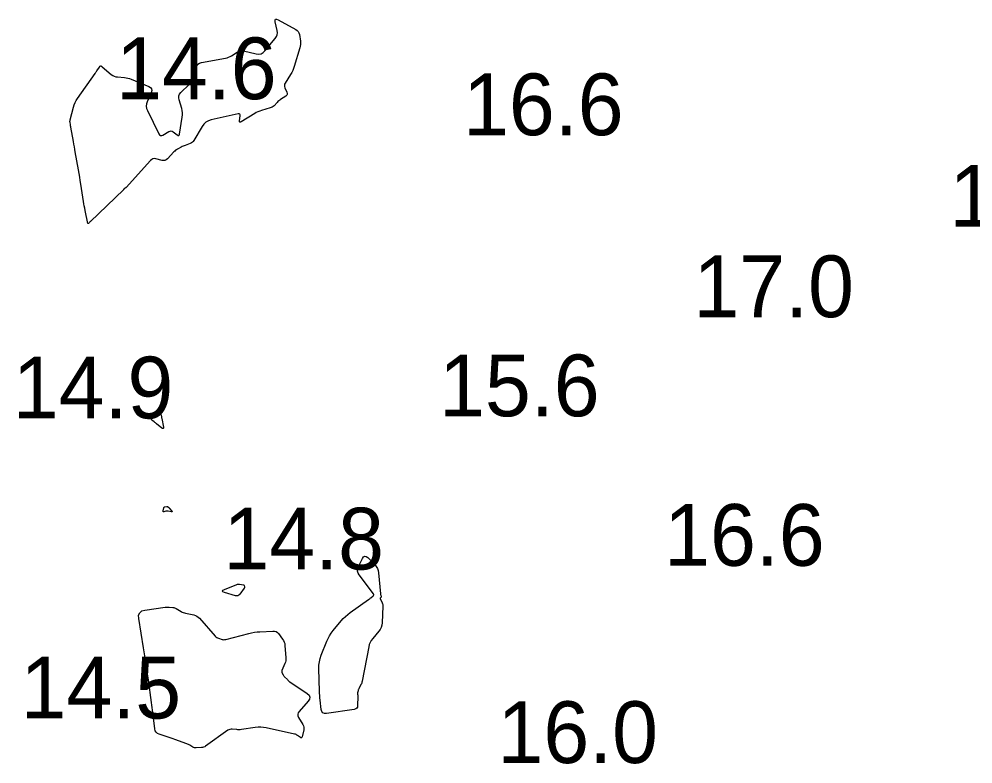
# Model space of a CAD drawing. Extents: x 3040093 to 3056816, y 408076 to 509144.
# Drawn here: x 3044731.9 to 3044809.2, y 434643.6 to 434703.9 of the extents above; entities that cross this region are included whole.
import ezdxf

# ---------------------------------------------------------------- set-up
doc = ezdxf.new("R2010")
doc.units = 0
doc.layers.add('V-CHAN-CONT-EL15', color=7, linetype='Continuous')
doc.layers.add('V-TOPO-SOUN-0810', color=7, linetype='Continuous')

msp = doc.modelspace()

# ---------------------------------------------------------------- linework, layer by layer
at = {"layer": 'V-CHAN-CONT-EL15'}
for points in [[(3044754.701, 434701.97), (3044754.699, 434701.836), (3044754.682, 434701.702), (3044754.65, 434701.57), (3044754.191, 434700.05), (3044754.135, 434699.885), (3044754.069, 434699.725), (3044753.992, 434699.569), (3044753.904, 434699.419), (3044753.457, 434698.705), (3044753.414, 434698.617), (3044753.396, 434698.527), (3044753.402, 434698.435), (3044753.433, 434698.342), (3044753.606, 434697.966), (3044753.634, 434697.876), (3044753.628, 434697.796), (3044753.59, 434697.725), (3044753.52, 434697.664), (3044753.093, 434697.382), (3044753.017, 434697.329), (3044752.945, 434697.272), (3044752.876, 434697.212), (3044752.811, 434697.147), (3044752.556, 434696.881), (3044752.489, 434696.819), (3044752.416, 434696.768), (3044752.336, 434696.727), (3044752.251, 434696.697), (3044751.542, 434696.495), (3044751.397, 434696.448), (3044751.256, 434696.391), (3044751.119, 434696.325), (3044750.987, 434696.248), (3044749.903, 434695.57), (3044749.829, 434695.535), (3044749.78, 434695.539), (3044749.757, 434695.582), (3044749.759, 434695.664), (3044749.817, 434696.068), (3044749.818, 434696.154), (3044749.79, 434696.208), (3044749.733, 434696.232), (3044749.647, 434696.226), (3044747.464, 434695.74), (3044747.233, 434695.665), (3044747.032, 434695.549), (3044746.861, 434695.393), (3044746.72, 434695.195), (3044746.066, 434694.068), (3044746.009, 434693.985), (3044745.94, 434693.916), (3044745.86, 434693.861), (3044745.769, 434693.819), (3044745.351, 434693.668), (3044745.269, 434693.637), (3044745.188, 434693.602), (3044745.109, 434693.565), (3044745.031, 434693.526), (3044744.721, 434693.361), (3044744.645, 434693.316), (3044744.575, 434693.266), (3044744.508, 434693.211), (3044744.446, 434693.149), (3044743.914, 434692.575), (3044743.821, 434692.496), (3044743.718, 434692.448), (3044743.605, 434692.432), (3044743.483, 434692.449), (3044742.977, 434692.58), (3044742.855, 434692.596), (3044742.743, 434692.58), (3044742.641, 434692.532), (3044742.548, 434692.451), (3044740.564, 434690.262), (3044740.548, 434690.245), (3044740.531, 434690.228), (3044740.513, 434690.212), (3044740.495, 434690.197), (3044740.42, 434690.139), (3044740.402, 434690.124), (3044740.383, 434690.108), (3044740.366, 434690.093), (3044740.348, 434690.076), (3044737.67, 434687.507), (3044737.661, 434687.498), (3044737.652, 434687.489), (3044737.644, 434687.479), (3044737.636, 434687.47), (3044737.605, 434687.43), (3044737.597, 434687.421), (3044737.589, 434687.412), (3044737.581, 434687.403), (3044737.571, 434687.394), (3044737.51, 434687.339), (3044737.498, 434687.331), (3044737.488, 434687.33), (3044737.481, 434687.336), (3044737.476, 434687.35), (3044737.251, 434688.4), (3044737.214, 434688.581), (3044737.179, 434688.762), (3044737.147, 434688.944), (3044737.117, 434689.127), (3044736.9, 434690.518), (3044736.853, 434690.81), (3044736.805, 434691.103), (3044736.756, 434691.395), (3044736.705, 434691.687), (3044736.448, 434693.136), (3044736.411, 434693.345), (3044736.373, 434693.555), (3044736.336, 434693.765), (3044736.298, 434693.975), (3044736.088, 434695.133), (3044736.079, 434695.183), (3044736.071, 434695.233), (3044736.062, 434695.284), (3044736.054, 434695.334), (3044736.022, 434695.535), (3044736.017, 434695.586), (3044736.016, 434695.636), (3044736.021, 434695.685), (3044736.032, 434695.735), (3044736.3, 434696.77), (3044736.357, 434696.955), (3044736.43, 434697.133), (3044736.518, 434697.304), (3044736.623, 434697.467), (3044738.049, 434699.495), (3044738.085, 434699.547), (3044738.122, 434699.598), (3044738.158, 434699.65), (3044738.195, 434699.701), (3044738.407, 434699.996), (3044738.411, 434700.002), (3044738.415, 434700.01), (3044738.418, 434700.018), (3044738.419, 434700.026), (3044738.425, 434700.059), (3044738.427, 434700.066), (3044738.431, 434700.072), (3044738.436, 434700.076), (3044738.444, 434700.079), (3044738.529, 434700.1), (3044738.539, 434700.101), (3044738.548, 434700.1), (3044738.555, 434700.096), (3044738.563, 434700.089), (3044738.589, 434700.059), (3044738.596, 434700.051), (3044738.604, 434700.044), (3044738.611, 434700.037), (3044738.619, 434700.031), (3044739.368, 434699.415), (3044739.481, 434699.335), (3044739.602, 434699.275), (3044739.731, 434699.233), (3044739.867, 434699.211), (3044740.43, 434699.16), (3044740.57, 434699.143), (3044740.707, 434699.115), (3044740.841, 434699.077), (3044740.973, 434699.029), (3044742.402, 434698.447), (3044742.553, 434698.358), (3044742.638, 434698.243), (3044742.656, 434698.101), (3044742.607, 434697.932), (3044742.277, 434697.204), (3044742.216, 434697.023), (3044742.198, 434696.842), (3044742.222, 434696.662), (3044742.289, 434696.482), (3044743.222, 434694.604), (3044743.285, 434694.511), (3044743.362, 434694.464), (3044743.453, 434694.462), (3044743.556, 434694.505), (3044744.041, 434694.793), (3044744.128, 434694.831), (3044744.214, 434694.84), (3044744.298, 434694.819), (3044744.379, 434694.77), (3044744.702, 434694.513), (3044744.775, 434694.469), (3044744.832, 434694.467), (3044744.872, 434694.507), (3044744.897, 434694.588), (3044745.123, 434695.951), (3044745.142, 434696.13), (3044745.14, 434696.307), (3044745.118, 434696.483), (3044745.074, 434696.657), (3044744.859, 434697.351), (3044744.828, 434697.519), (3044744.843, 434697.674), (3044744.905, 434697.818), (3044745.013, 434697.95), (3044745.691, 434698.603), (3044745.815, 434698.739), (3044745.916, 434698.888), (3044745.994, 434699.049), (3044746.051, 434699.224), (3044746.232, 434699.947), (3044746.295, 434700.109), (3044746.392, 434700.235), (3044746.524, 434700.324), (3044746.69, 434700.375), (3044748.616, 434700.727), (3044748.748, 434700.758), (3044748.876, 434700.801), (3044748.998, 434700.858), (3044749.115, 434700.927), (3044749.573, 434701.23), (3044749.69, 434701.292), (3044749.811, 434701.328), (3044749.938, 434701.337), (3044750.069, 434701.319), (3044751.104, 434701.08), (3044751.312, 434701.058), (3044751.501, 434701.091), (3044751.671, 434701.179), (3044751.823, 434701.323), (3044752.66, 434702.331), (3044752.756, 434702.474), (3044752.813, 434702.627), (3044752.832, 434702.789), (3044752.812, 434702.961), (3044752.657, 434703.665), (3044752.642, 434703.809), (3044752.677, 434703.886), (3044752.762, 434703.898), (3044752.895, 434703.844), (3044754.326, 434703.056), (3044754.435, 434702.981), (3044754.518, 434702.888), (3044754.575, 434702.778), (3044754.608, 434702.651), (3044754.689, 434702.106)], [(3044743.433, 434671.644), (3044743.44, 434671.606), (3044743.455, 434671.531), (3044743.586, 434670.848), (3044743.594, 434670.761), (3044743.575, 434670.719), (3044743.528, 434670.722), (3044743.455, 434670.769), (3044743.025, 434671.117), (3044742.981, 434671.153), (3044742.936, 434671.189), (3044742.891, 434671.225), (3044742.846, 434671.262), (3044742.655, 434671.415), (3044742.626, 434671.447), (3044742.615, 434671.48), (3044742.622, 434671.514), (3044742.648, 434671.549), (3044742.829, 434671.732), (3044742.844, 434671.746), (3044742.861, 434671.757), (3044742.879, 434671.766), (3044742.898, 434671.773), (3044742.979, 434671.794), (3044742.999, 434671.799), (3044743.019, 434671.805), (3044743.039, 434671.81), (3044743.059, 434671.816), (3044743.309, 434671.886), (3044743.342, 434671.891), (3044743.368, 434671.883), (3044743.386, 434671.863), (3044743.397, 434671.832)], [(3044744.044, 434664.306), (3044744.06, 434664.289), (3044744.076, 434664.271), (3044744.091, 434664.253), (3044744.265, 434664.04), (3044744.288, 434664.004), (3044744.29, 434663.982), (3044744.269, 434663.972), (3044744.227, 434663.975), (3044743.967, 434664.023), (3044743.924, 434664.029), (3044743.882, 434664.03), (3044743.84, 434664.027), (3044743.798, 434664.021), (3044743.63, 434663.985), (3044743.594, 434663.983), (3044743.572, 434663.993), (3044743.562, 434664.016), (3044743.566, 434664.051), (3044743.625, 434664.301), (3044743.637, 434664.332), (3044743.655, 434664.356), (3044743.68, 434664.373), (3044743.712, 434664.383), (3044743.877, 434664.411), (3044743.9, 434664.413), (3044743.921, 434664.409), (3044743.94, 434664.4), (3044743.958, 434664.387), (3044744.027, 434664.322)], [(3044761.246, 434657.099), (3044761.245, 434657.084), (3044761.239, 434657.069), (3044761.227, 434657.056), (3044761.173, 434657.005), (3044761.162, 434656.992), (3044761.156, 434656.977), (3044761.156, 434656.962), (3044761.161, 434656.946), (3044761.323, 434656.601), (3044761.349, 434656.537), (3044761.366, 434656.472), (3044761.376, 434656.405), (3044761.377, 434656.336), (3044761.326, 434654.977), (3044761.304, 434654.791), (3044761.252, 434654.616), (3044761.17, 434654.453), (3044761.058, 434654.302), (3044760.552, 434653.721), (3044760.437, 434653.57), (3044760.345, 434653.408), (3044760.275, 434653.235), (3044760.228, 434653.051), (3044759.702, 434650.27), (3044759.685, 434650.194), (3044759.662, 434650.121), (3044759.634, 434650.049), (3044759.6, 434649.979), (3044759.419, 434649.634), (3044759.402, 434649.599), (3044759.388, 434649.564), (3044759.376, 434649.528), (3044759.367, 434649.491), (3044759.328, 434649.312), (3044759.324, 434649.289), (3044759.322, 434649.266), (3044759.324, 434649.243), (3044759.327, 434649.22), (3044759.347, 434649.127), (3044759.351, 434649.104), (3044759.353, 434649.08), (3044759.355, 434649.057), (3044759.355, 434649.033), (3044759.333, 434648.282), (3044759.313, 434648.163), (3044759.261, 434648.073), (3044759.177, 434648.011), (3044759.061, 434647.977), (3044756.809, 434647.646), (3044756.643, 434647.646), (3044756.517, 434647.699), (3044756.433, 434647.806), (3044756.389, 434647.966), (3044756.296, 434648.714), (3044756.275, 434648.901), (3044756.258, 434649.089), (3044756.246, 434649.277), (3044756.239, 434649.465), (3044756.192, 434651.262), (3044756.198, 434651.546), (3044756.233, 434651.825), (3044756.296, 434652.099), (3044756.388, 434652.369), (3044756.834, 434653.496), (3044756.936, 434653.727), (3044757.055, 434653.948), (3044757.191, 434654.158), (3044757.345, 434654.359), (3044757.994, 434655.14), (3044758.162, 434655.329), (3044758.341, 434655.506), (3044758.532, 434655.671), (3044758.733, 434655.823), (3044760.212, 434656.869), (3044760.261, 434656.904), (3044760.309, 434656.94), (3044760.356, 434656.976), (3044760.403, 434657.014), (3044760.59, 434657.166), (3044760.626, 434657.205), (3044760.642, 434657.247), (3044760.637, 434657.291), (3044760.611, 434657.338), (3044759.452, 434658.865), (3044759.362, 434659.019), (3044759.321, 434659.178), (3044759.329, 434659.342), (3044759.387, 434659.511), (3044759.719, 434660.198), (3044759.808, 434660.331), (3044759.91, 434660.388), (3044760.025, 434660.368), (3044760.154, 434660.272), (3044760.719, 434659.707), (3044760.843, 434659.561), (3044760.936, 434659.401), (3044760.999, 434659.226), (3044761.032, 434659.038), (3044761.183, 434657.331), (3044761.186, 434657.305), (3044761.19, 434657.279), (3044761.197, 434657.254), (3044761.204, 434657.229), (3044761.243, 434657.116)], [(3044750.097, 434658.056), (3044750.116, 434658.043), (3044750.129, 434658.024), (3044750.137, 434658.001), (3044750.159, 434657.894), (3044750.162, 434657.868), (3044750.16, 434657.843), (3044750.152, 434657.82), (3044750.138, 434657.797), (3044749.773, 434657.301), (3044749.702, 434657.226), (3044749.621, 434657.182), (3044749.529, 434657.168), (3044749.427, 434657.184), (3044748.553, 434657.444), (3044748.416, 434657.5), (3044748.368, 434657.561), (3044748.41, 434657.625), (3044748.541, 434657.694), (3044749.533, 434658.097), (3044749.59, 434658.116), (3044749.648, 434658.126), (3044749.707, 434658.128), (3044749.766, 434658.121), (3044750.073, 434658.064)], [(3044753.687, 434650.335), (3044753.739, 434650.29), (3044753.793, 434650.247), (3044753.85, 434650.206), (3044755.241, 434649.254), (3044755.391, 434649.117), (3044755.453, 434648.968), (3044755.429, 434648.809), (3044755.317, 434648.64), (3044754.589, 434647.816), (3044754.51, 434647.7), (3044754.477, 434647.58), (3044754.488, 434647.456), (3044754.543, 434647.328), (3044754.888, 434646.752), (3044754.938, 434646.647), (3044754.967, 434646.538), (3044754.974, 434646.427), (3044754.959, 434646.311), (3044754.831, 434645.744), (3044754.811, 434645.69), (3044754.781, 434645.663), (3044754.741, 434645.664), (3044754.691, 434645.693), (3044754.47, 434645.862), (3044754.413, 434645.901), (3044754.353, 434645.933), (3044754.29, 434645.959), (3044754.223, 434645.977), (3044751.909, 434646.481), (3044751.692, 434646.518), (3044751.475, 434646.536), (3044751.257, 434646.533), (3044751.038, 434646.511), (3044749.91, 434646.344), (3044749.817, 434646.333), (3044749.724, 434646.328), (3044749.631, 434646.329), (3044749.538, 434646.335), (3044749.165, 434646.373), (3044749.073, 434646.375), (3044748.987, 434646.36), (3044748.904, 434646.33), (3044748.825, 434646.284), (3044747.015, 434644.999), (3044746.935, 434644.95), (3044746.851, 434644.914), (3044746.762, 434644.89), (3044746.669, 434644.879), (3044746.24, 434644.856), (3044746.17, 434644.858), (3044746.103, 434644.869), (3044746.039, 434644.891), (3044745.977, 434644.922), (3044745.736, 434645.07), (3044745.674, 434645.105), (3044745.611, 434645.137), (3044745.547, 434645.166), (3044745.481, 434645.191), (3044744.527, 434645.53), (3044744.368, 434645.586), (3044744.209, 434645.641), (3044744.05, 434645.695), (3044743.89, 434645.748), (3044743.251, 434645.957), (3044743.108, 434646.024), (3044743.001, 434646.119), (3044742.928, 434646.243), (3044742.89, 434646.396), (3044742.729, 434647.712), (3044742.704, 434647.917), (3044742.678, 434648.122), (3044742.652, 434648.327), (3044742.625, 434648.532), (3044742.518, 434649.351), (3044742.49, 434649.556), (3044742.462, 434649.761), (3044742.432, 434649.965), (3044742.402, 434650.17), (3044742.171, 434651.679), (3044742.122, 434651.998), (3044742.073, 434652.318), (3044742.023, 434652.637), (3044741.972, 434652.957), (3044741.59, 434655.339), (3044741.585, 434655.606), (3044741.668, 434655.809), (3044741.838, 434655.948), (3044742.094, 434656.023), (3044743.746, 434656.257), (3044743.821, 434656.265), (3044743.896, 434656.27), (3044743.972, 434656.27), (3044744.047, 434656.266), (3044744.348, 434656.243), (3044744.422, 434656.233), (3044744.494, 434656.215), (3044744.562, 434656.188), (3044744.628, 434656.153), (3044745.017, 434655.914), (3044745.105, 434655.865), (3044745.196, 434655.824), (3044745.291, 434655.792), (3044745.388, 434655.767), (3044746.043, 434655.631), (3044746.18, 434655.592), (3044746.304, 434655.532), (3044746.417, 434655.453), (3044746.519, 434655.354), (3044747.793, 434653.895), (3044747.848, 434653.841), (3044747.908, 434653.796), (3044747.974, 434653.76), (3044748.045, 434653.734), (3044748.345, 434653.647), (3044748.42, 434653.63), (3044748.495, 434653.624), (3044748.57, 434653.628), (3044748.645, 434653.642), (3044750.523, 434654.13), (3044750.741, 434654.18), (3044750.96, 434654.22), (3044751.181, 434654.248), (3044751.404, 434654.265), (3044752.467, 434654.319), (3044752.6, 434654.311), (3044752.718, 434654.274), (3044752.824, 434654.207), (3044752.915, 434654.111), (3044753.253, 434653.666), (3044753.328, 434653.551), (3044753.384, 434653.429), (3044753.422, 434653.301), (3044753.441, 434653.165), (3044753.511, 434652.143), (3044753.512, 434652.027), (3044753.5, 434651.913), (3044753.473, 434651.801), (3044753.434, 434651.692), (3044753.195, 434651.139), (3044753.18, 434651.092), (3044753.176, 434651.046), (3044753.183, 434650.999), (3044753.201, 434650.954), (3044753.296, 434650.772), (3044753.321, 434650.727), (3044753.349, 434650.685), (3044753.381, 434650.645), (3044753.415, 434650.608), (3044753.637, 434650.384)]]:
    msp.add_lwpolyline(points, close=True, dxfattribs=at)

# ---------------------------------------------------------------- texts
at = {"layer": 'V-TOPO-SOUN-0810'}
for s, p in [('14.6 ', (3044739.753, 434697.41)), ('16.6 ', (3044767.873, 434694.49)), ('17.5 ', (3044807.303, 434687.07)), ('17.0 ', (3044786.543, 434679.75)), ('14.9 ', (3044731.383, 434671.55)), ('15.6 ', (3044765.933, 434671.72)), ('16.6 ', (3044784.173, 434659.61)), ('14.8 ', (3044748.453, 434659.31)), ('14.5 ', (3044732.013, 434647.24)), ('16.0 ', (3044770.663, 434643.63))]:
    msp.add_text(s, height=5, dxfattribs=at).set_placement(p)

doc.saveas('drawing.dxf')
